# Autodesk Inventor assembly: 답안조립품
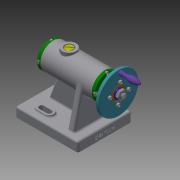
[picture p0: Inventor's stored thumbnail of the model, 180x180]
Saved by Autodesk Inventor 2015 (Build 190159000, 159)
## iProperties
Created: 2022-06
Part Number: 답안조립품
Document SubType Name: Assembly
Designer: 104-1
Author: 104-1
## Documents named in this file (18)
- C:\Users\104-1\Desktop\720606V1002\답안조립품.iam
- C:\Users\104-1\Desktop\720606V1002\나사.ipt
- C:\Users\104-1\Desktop\720606V1002\나사축.ipt
- C:\Users\104-1\Desktop\720606V1002\너트 M8.ipt
- C:\Users\104-1\Desktop\720606V1002\돌림판.ipt
- C:\Users\104-1\Desktop\720606V1002\멈춤나사 M3.ipt
- C:\Users\104-1\Desktop\720606V1002\본체.ipt
- C:\Users\104-1\Desktop\720606V1002\볼트 M3.ipt
- C:\Users\104-1\Desktop\720606V1002\부시.ipt
- C:\Users\104-1\Desktop\720606V1002\센터.ipt
- C:\Users\104-1\Desktop\720606V1002\센터홀더.ipt
- C:\Users\104-1\Desktop\720606V1002\슬리브.ipt
- C:\Users\104-1\Desktop\720606V1002\와셔.ipt
- C:\Users\104-1\Desktop\720606V1002\중공축.ipt
- C:\Users\104-1\Desktop\720606V1002\커버.ipt
- C:\Users\104-1\Desktop\720606V1002\키 4 x 4 x 10.ipt
- C:\Users\104-1\Desktop\720606V1002\플랜지.ipt
- C:\Users\104-1\Desktop\720606V1002\핸들.ipt
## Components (2 placed, 2 different names)
1. 플랜지:1 — 각도:2
2. 핸들:1
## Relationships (1: Angle 1)
- 각도:2 [Angle]: 플랜지:1
